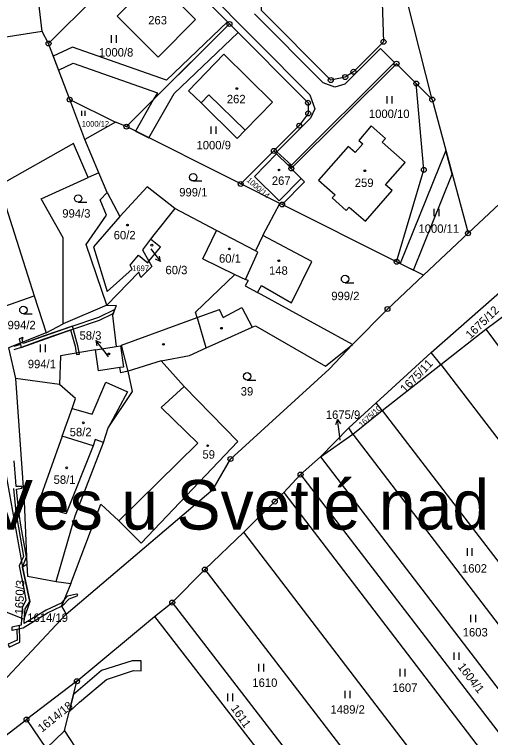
# Model space of a CAD drawing. Extents: x -680203 to -673936, y -1102717 to -1093650.
# Drawn here: x -676580.5 to -676484.3, y -1100983.9 to -1100837.8 of the extents above; entities that cross this region are included whole.
import ezdxf

# ---------------------------------------------------------------- set-up
doc = ezdxf.new("R2010")
doc.units = 0
for name, color, linetype in [('SOxx02xx_Koleje_param další_Popis10', 7, 'Continuous'), ('SOxx02xx_Staničení_Popis10', 7, 'Continuous'), ('SOxxxxxx_Koleje_hlavní_body_Popis10', 7, 'Continuous'), ('SOxxxxxx_Koleje_LN_parametry_Popis10', 7, 'Continuous'), ('SOxxxxxx_Koleje_param další_Popis10', 7, 'Continuous'), ('SOxxxxxx_Osa_bod_P', 7, 'Continuous'), ('SOxxxxxx_Staničení_Popis10', 7, 'Continuous'), ('x_prac', 7, 'Continuous')]:
    doc.layers.add(name, color=color, linetype=linetype)

msp = doc.modelspace()

# ---------------------------------------------------------------- linework, layer by layer
at = {"layer": 'SOxx02xx_Koleje_param další_Popis10'}
for centre, radius in [((-676537.07, -1100839.74), 0.5), ((-676537.07, -1100839.74), 0.0303), ((-676505.95, -1100843.34), 0.5), ((-676573.65, -1100843.69), 0.5), ((-676573.65, -1100843.69), 0.0303), ((-676505.95, -1100843.34), 0.0303), ((-676503.33, -1100847.76), 0.5), ((-676503.33, -1100847.76), 0.0303), ((-676513.7, -1100850.47), 0.5), ((-676512.04, -1100849.4), 0.5), ((-676512.04, -1100849.4), 0.0303), ((-676516.62, -1100851.07), 0.5), ((-676516.62, -1100851.07), 0.0303), ((-676513.7, -1100850.47), 0.0303), ((-676499.34, -1100851.78), 0.5), ((-676499.34, -1100851.78), 0.0303), ((-676569.37, -1100855.03), 0.5), ((-676496.12, -1100855.01), 0.5), ((-676569.37, -1100855.03), 0.0303), ((-676521.22, -1100855.66), 0.5), ((-676521.22, -1100855.66), 0.0303), ((-676496.12, -1100855.01), 0.0303), ((-676521.18, -1100857.82), 0.5), ((-676521.18, -1100857.82), 0.0303), ((-676557.91, -1100860.48), 0.5), ((-676522.98, -1100860.28), 0.5), ((-676522.98, -1100860.28), 0.0303), ((-676557.91, -1100860.48), 0.0303), ((-676528.12, -1100865.39), 0.5), ((-676528.12, -1100865.39), 0.0303), ((-676524.59, -1100868.94), 0.5), ((-676524.59, -1100868.94), 0.0303), ((-676497.82, -1100869.21), 0.5), ((-676497.82, -1100869.21), 0.0303), ((-676534.82, -1100872.06), 0.5), ((-676534.82, -1100872.06), 0.0303), ((-676526.44, -1100876.21), 0.5), ((-676526.44, -1100876.21), 0.0303), ((-676488.89, -1100882.02), 0.5), ((-676488.89, -1100882.02), 0.0303), ((-676503.31, -1100887.77), 0.5), ((-676503.31, -1100887.77), 0.0303), ((-676505.16, -1100897.32), 0.5), ((-676505.16, -1100897.32), 0.0303), ((-676536.89, -1100927.63), 0.5), ((-676536.89, -1100927.63), 0.0303), ((-676522.72, -1100930.77), 0.5), ((-676522.72, -1100930.77), 0.0303), ((-676527.93, -1100936.22), 0.5), ((-676527.93, -1100936.22), 0.0303), ((-676542.07, -1100949.94), 0.5), ((-676542.07, -1100949.94), 0.0303), ((-676548.66, -1100956.62), 0.5), ((-676548.66, -1100956.62), 0.0303), ((-676567.91, -1100972.52), 0.5), ((-676567.91, -1100972.52), 0.0303), ((-676578.1, -1100980.26), 0.5), ((-676578.1, -1100980.26), 0.0303)]:
    msp.add_circle(centre, radius, dxfattribs=at)
at = {"layer": 'SOxx02xx_Staničení_Popis10'}
for p, q in [((-676553.01, -1100885.15), (-676552.85, -1100885.36)), ((-676552.85, -1100885.36), (-676551, -1100887.73)), ((-676551, -1100887.73), (-676551.22, -1100886.63)), ((-676551, -1100887.73), (-676552.01, -1100887.24)), ((-676562.23, -1100906.06), (-676564.08, -1100903.7)), ((-676564.08, -1100903.7), (-676563.07, -1100904.18)), ((-676564.08, -1100903.7), (-676563.86, -1100904.79)), ((-676561.55, -1100906.96), (-676562.23, -1100906.06)), ((-676515.29, -1100919.63), (-676515.64, -1100920.69)), ((-676514.87, -1100922.6), (-676515.29, -1100919.63)), ((-676515.29, -1100919.63), (-676514.65, -1100920.55)), ((-676514.71, -1100923.8), (-676514.87, -1100922.6))]:
    msp.add_line(p, q, dxfattribs=at)
at = {"layer": 'SOxxxxxx_Koleje_hlavní_body_Popis10'}
for p, q in [((-676560.9, -1100843.53), (-676560.9, -1100842.03)), ((-676559.9, -1100843.53), (-676559.9, -1100842.03)), ((-676505.21, -1100855.8), (-676505.21, -1100854.3)), ((-676504.21, -1100855.8), (-676504.21, -1100854.3)), ((-676566.91, -1100858.32), (-676566.91, -1100857.31)), ((-676566.24, -1100858.32), (-676566.24, -1100857.31)), ((-676540.76, -1100861.95), (-676540.76, -1100860.45)), ((-676539.76, -1100861.95), (-676539.76, -1100860.45)), ((-676544.41, -1100871.46), (-676542.66, -1100871.46)), ((-676567.65, -1100875.74), (-676565.9, -1100875.74)), ((-676495.71, -1100878.6), (-676495.71, -1100877.1)), ((-676494.71, -1100878.6), (-676494.71, -1100877.1)), ((-676513.73, -1100892.01), (-676511.98, -1100892.01)), ((-676578.73, -1100898.28), (-676576.98, -1100898.28)), ((-676575.26, -1100906.01), (-676575.26, -1100904.51)), ((-676574.26, -1100906.01), (-676574.26, -1100904.51)), ((-676533.52, -1100911.68), (-676531.77, -1100911.68)), ((-676489.02, -1100947.15), (-676489.02, -1100945.65)), ((-676488.02, -1100947.15), (-676488.02, -1100945.65)), ((-676488.33, -1100960.59), (-676488.33, -1100959.09)), ((-676487.33, -1100960.59), (-676487.33, -1100959.09)), ((-676491.69, -1100968.19), (-676491.69, -1100966.69)), ((-676490.69, -1100968.19), (-676490.69, -1100966.69)), ((-676531.14, -1100970.52), (-676531.14, -1100969.02)), ((-676530.14, -1100970.52), (-676530.14, -1100969.02)), ((-676502.57, -1100971.54), (-676502.57, -1100970.04)), ((-676501.57, -1100971.54), (-676501.57, -1100970.04)), ((-676537.43, -1100976.51), (-676537.43, -1100975.01)), ((-676536.43, -1100976.51), (-676536.43, -1100975.01)), ((-676513.68, -1100975.95), (-676513.68, -1100974.45)), ((-676512.68, -1100975.95), (-676512.68, -1100974.45))]:
    msp.add_line(p, q, dxfattribs=at)
for centre in [(-676544.41, -1100870.71), (-676567.65, -1100874.99), (-676513.73, -1100891.26), (-676578.73, -1100897.53), (-676533.52, -1100910.93)]:
    msp.add_circle(centre, 0.75, dxfattribs=at)
at = {"layer": 'SOxxxxxx_Koleje_LN_parametry_Popis10'}
for points in [[(-676552.48, -1100855.08), (-676537.07, -1100839.74), (-676537.48, -1100839.33), (-676549.84, -1100851.11), (-676568.84, -1100844.43), (-676572.68, -1100846.26), (-676571.63, -1100849.06), (-676568.67, -1100847.67), (-676551.66, -1100853.64)], [(-676548.27, -1100853.76), (-676535.36, -1100841.46), (-676537.07, -1100839.74), (-676552.48, -1100855.08), (-676556.09, -1100861.4), (-676553.41, -1100862.74)], [(-676493.37, -1100865.28), (-676502.61, -1100888.12), (-676499.92, -1100889.46), (-676492.09, -1100870.08)], [(-676579.2, -1100905.11), (-676568.91, -1100901.46), (-676563.36, -1100899.57), (-676560.57, -1100898.24), (-676560.28, -1100897.44), (-676563.58, -1100899.01), (-676569.11, -1100900.9), (-676578.78, -1100904.31), (-676578.85, -1100904.01), (-676579.41, -1100904.23)], [(-676578.85, -1100904.01), (-676579.01, -1100903.36), (-676578.79, -1100903.28), (-676578.87, -1100903.07), (-676579.58, -1100903.34), (-676579.37, -1100904.22)], [(-676567.39, -1100906.42), (-676567.44, -1100906.13), (-676568.04, -1100906.23), (-676567.98, -1100906.53)], [(-676570.49, -1100956.08), (-676571.01, -1100957.33), (-676570.76, -1100957.23), (-676569.47, -1100955.87), (-676567.85, -1100955.26), (-676567.75, -1100954.97), (-676567.97, -1100954.9), (-676569.79, -1100955.35)], [(-676579.42, -1100964.61), (-676579.49, -1100961.26), (-676581.06, -1100961.59), (-676581.04, -1100962.18), (-676580.07, -1100962), (-676580.02, -1100964.23), (-676581.78, -1100965.05), (-676581.61, -1100965.64)], [(-676562.96, -1100970.38), (-676568.58, -1100975.17), (-676569.47, -1100978.73), (-676567.36, -1100976.76), (-676561.97, -1100972.16), (-676556.45, -1100970.38), (-676554.95, -1100970.42), (-676554.9, -1100968.42), (-676556.74, -1100968.38)]]:
    msp.add_lwpolyline(points, close=True, dxfattribs=at)
for points in [[(-676580.58, -1100905.53), (-676578.89, -1100904.99), (-676574.53, -1100903.37), (-676569.21, -1100901.56), (-676568.29, -1100904.86), (-676568.04, -1100906.23), (-676567.44, -1100906.13), (-676567.7, -1100904.75), (-676568.81, -1100900.8), (-676574.73, -1100902.81), (-676578.78, -1100904.31), (-676578.85, -1100904.01), (-676579.37, -1100904.22), (-676579.32, -1100904.5), (-676580.63, -1100904.92)], [(-676581.03, -1100962.22), (-676578.78, -1100961.7), (-676573.85, -1100958.7), (-676571.01, -1100957.33), (-676570.49, -1100956.08), (-676571.12, -1100956.73), (-676574.13, -1100958.18), (-676578.56, -1100960.87), (-676578.48, -1100959.46), (-676578.39, -1100957.86), (-676577.42, -1100956.4), (-676578.91, -1100949.49), (-676578.11, -1100947.4), (-676579.15, -1100941.37), (-676579.67, -1100938.29), (-676580.11, -1100933.74), (-676579.02, -1100933.5), (-676579.01, -1100933.17), (-676580.16, -1100933.18), (-676580.27, -1100932.15), (-676580.56, -1100928)], [(-676580.73, -1100933.56), (-676580.27, -1100938.37), (-676579.75, -1100941.47), (-676578.72, -1100947.32), (-676579.14, -1100948.19), (-676579.61, -1100949.18), (-676578.61, -1100953.83), (-676578.21, -1100956.14), (-676578.99, -1100957.7), (-676579.1, -1100959.82), (-676579.18, -1100961.18), (-676581.06, -1100961.61)]]:
    msp.add_lwpolyline(points, dxfattribs=at)
at = {"layer": 'SOxxxxxx_Koleje_param další_Popis10'}
for centre in [(-676535.58, -1100852.79), (-676527.08, -1100869.24), (-676509.72, -1100869.39), (-676557.71, -1100880.37), (-676552.77, -1100884.42), (-676537.12, -1100885.18), (-676527.11, -1100887.58), (-676538.72, -1100901.2), (-676550.44, -1100904.46), (-676561.48, -1100906.39), (-676566.62, -1100920.31), (-676541.5, -1100924.93), (-676569.98, -1100929.4)]:
    msp.add_circle(centre, 0.175, dxfattribs=at)
at = {"layer": 'SOxxxxxx_Staničení_Popis10'}
for p, q in [((-676542.84, -1100855.67), (-676541.23, -1100854.03)), ((-676541.23, -1100854.03), (-676533.95, -1100861.17)), ((-676525.19, -1100868.34), (-676524.83, -1100868.7)), ((-676583.69, -1100872.39), (-676576.54, -1100894.64)), ((-676542.46, -1100887.2), (-676539.7, -1100881.46)), ((-676542.46, -1100887.2), (-676536.01, -1100890.37)), ((-676533.33, -1100891.54), (-676533.95, -1100892.65)), ((-676533.33, -1100891.54), (-676533.85, -1100891.33)), ((-676533.95, -1100892.65), (-676531.41, -1100893.98)), ((-676543.61, -1100899.04), (-676539.11, -1100897.4)), ((-676538.38, -1100899.04), (-676539.11, -1100897.4)), ((-676538.38, -1100899.04), (-676534.62, -1100897.05)), ((-676534.62, -1100897.05), (-676532.51, -1100901.02)), ((-676558.93, -1100904.62), (-676543.61, -1100899.04)), ((-676557.56, -1100909.88), (-676558.93, -1100904.62)), ((-676564.86, -1100918.59), (-676562.1, -1100912.09)), ((-676562.1, -1100912.09), (-676557.72, -1100914.08)), ((-676557.72, -1100914.08), (-676561.58, -1100921.3)), ((-676546.25, -1100913), (-676550.91, -1100917.24)), ((-676550.91, -1100917.24), (-676543.47, -1100924.45)), ((-676568.89, -1100917.42), (-676564.86, -1100918.59)), ((-676570.87, -1100922.98), (-676575.9, -1100937.01)), ((-676543.47, -1100924.45), (-676559.47, -1100940.1)), ((-676564.6, -1100924.95), (-676570.07, -1100938.66)), ((-676575.9, -1100937.01), (-676570.07, -1100938.66))]:
    msp.add_line(p, q, dxfattribs=at)
at = {"layer": 'x_prac'}
for p, q in [((-676574.95, -1100841.25), (-676579.72, -1100801.4)), ((-676573.65, -1100843.69), (-676553.3, -1100823.44)), ((-676553.3, -1100823.44), (-676537.07, -1100839.74)), ((-676557.91, -1100860.48), (-676537.07, -1100839.74)), ((-676574.95, -1100841.25), (-676593.79, -1100844.19)), ((-676573.65, -1100843.69), (-676574.95, -1100841.25)), ((-676569.37, -1100855.03), (-676573.65, -1100843.69)), ((-676497.82, -1100869.21), (-676499.34, -1100851.78)), ((-676499.34, -1100851.78), (-676496.12, -1100855.01)), ((-676569.37, -1100855.03), (-676560.11, -1100859.6)), ((-676566.3, -1100863.11), (-676569.37, -1100855.03)), ((-676496.12, -1100855.01), (-676488.89, -1100882.02)), ((-676560.11, -1100859.6), (-676566.3, -1100863.11)), ((-676557.91, -1100860.48), (-676560.11, -1100859.6)), ((-676534.82, -1100872.06), (-676557.91, -1100860.48)), ((-676563.48, -1100869.8), (-676566.3, -1100863.11)), ((-676534.82, -1100872.06), (-676528.12, -1100865.39)), ((-676528.12, -1100865.39), (-676527.57, -1100865.95)), ((-676522.63, -1100870.94), (-676524.59, -1100868.94)), ((-676563.48, -1100869.8), (-676565.64, -1100870.73)), ((-676561.83, -1100873.76), (-676563.48, -1100869.8)), ((-676503.31, -1100887.77), (-676497.82, -1100869.21)), ((-676526.91, -1100875.99), (-676534.82, -1100872.06)), ((-676521.93, -1100871.65), (-676526.44, -1100876.21)), ((-676522.63, -1100870.94), (-676521.93, -1100871.65)), ((-676561.83, -1100873.76), (-676559.24, -1100878.61)), ((-676530.35, -1100882.47), (-676526.91, -1100875.99)), ((-676526.44, -1100876.21), (-676526.91, -1100875.99)), ((-676503.31, -1100887.77), (-676526.44, -1100876.21)), ((-676488.89, -1100882.02), (-676481.47, -1100875.04)), ((-676488.89, -1100882.02), (-676497.86, -1100890.48)), ((-676530.35, -1100882.47), (-676531.83, -1100885.6)), ((-676497.86, -1100890.48), (-676503.31, -1100887.77)), ((-676496.34, -1100906.08), (-676480.26, -1100891.99)), ((-676561.9, -1100896.53), (-676570.7, -1100900.34)), ((-676485.32, -1100901.42), (-676477.57, -1100895.67)), ((-676574.16, -1100902.14), (-676570.7, -1100900.34)), ((-676574.16, -1100902.14), (-676581.73, -1100905.16)), ((-676494.4, -1100908.54), (-676485.32, -1100901.42)), ((-676485.32, -1100901.42), (-676461.19, -1100934)), ((-676581.73, -1100905.16), (-676580.34, -1100911.36)), ((-676564.18, -1100905.58), (-676560, -1100904.88)), ((-676560, -1100904.88), (-676559.14, -1100904.74)), ((-676559.14, -1100904.74), (-676558.52, -1100909.06)), ((-676507.46, -1100916.27), (-676496.34, -1100906.08)), ((-676494.4, -1100908.54), (-676496.34, -1100906.08)), ((-676550.87, -1100907.8), (-676557.56, -1100909.88)), ((-676506.21, -1100917.85), (-676494.4, -1100908.54)), ((-676494.4, -1100908.54), (-676469.06, -1100941.58)), ((-676558.52, -1100909.06), (-676559.21, -1100909.16)), ((-676571.43, -1100912.59), (-676580.34, -1100911.36)), ((-676512.95, -1100921.3), (-676507.46, -1100916.27)), ((-676506.21, -1100917.85), (-676507.46, -1100916.27)), ((-676512.14, -1100922.61), (-676506.21, -1100917.85)), ((-676506.21, -1100917.85), (-676454.36, -1100985.53)), ((-676518.69, -1100927.16), (-676512.95, -1100921.3)), ((-676512.14, -1100922.61), (-676512.95, -1100921.3)), ((-676518.69, -1100927.16), (-676512.14, -1100922.61)), ((-676512.14, -1100922.61), (-676458.6, -1100992.67)), ((-676583.29, -1100924.99), (-676578.91, -1100949.49)), ((-676522.72, -1100930.77), (-676518.69, -1100927.16)), ((-676518.69, -1100927.16), (-676462.89, -1101000.14)), ((-676526.09, -1100934.37), (-676522.72, -1100930.77)), ((-676522.72, -1100930.77), (-676464.92, -1101006.1)), ((-676526.09, -1100934.37), (-676466.86, -1101011.76)), ((-676542.07, -1100949.94), (-676534.21, -1100942.4)), ((-676470.34, -1101025.78), (-676534.21, -1100942.4)), ((-676578.04, -1100948.93), (-676578.91, -1100949.49)), ((-676548.66, -1100956.62), (-676542.07, -1100949.94)), ((-676542.07, -1100949.94), (-676507.85, -1100994.4)), ((-676572.09, -1100952.4), (-676569.13, -1100952.77)), ((-676552.26, -1100959.44), (-676548.66, -1100956.62)), ((-676548.66, -1100956.62), (-676514.94, -1101000.3)), ((-676585.17, -1100975.07), (-676570.1, -1100958.94)), ((-676567.91, -1100972.52), (-676552.26, -1100959.44)), ((-676552.26, -1100959.44), (-676518.17, -1101003.34)), ((-676567.91, -1100972.52), (-676578.1, -1100980.26)), ((-676570.43, -1100982.53), (-676567.91, -1100972.52)), ((-676592.72, -1100991.36), (-676578.1, -1100980.26)), ((-676578.1, -1100980.26), (-676574.15, -1100986.08)), ((-676574.15, -1100986.08), (-676570.43, -1100982.53)), ((-676570.43, -1100982.53), (-676566.51, -1100988.48))]:
    msp.add_line(p, q, dxfattribs=at)
for points in [[(-676502.98, -1100809.33), (-676496.95, -1100812.05), (-676506.66, -1100823.48), (-676505.95, -1100843.34), (-676512.04, -1100849.4), (-676513.7, -1100850.47), (-676516.62, -1100851.07), (-676530.62, -1100837.01), (-676530.61, -1100833.47)], [(-676496.12, -1100855.01), (-676501.2, -1100835.05), (-676503.82, -1100826.27), (-676498.92, -1100820), (-676491.58, -1100824.01), (-676489.06, -1100817.06)], [(-676546.96, -1100830.61), (-676549.61, -1100828), (-676559.78, -1100838.17), (-676551.51, -1100846.45), (-676543.95, -1100838.86), (-676549.57, -1100833.24), (-676546.96, -1100830.61)], [(-676542.41, -1100832.29), (-676520.82, -1100854.03), (-676519.82, -1100856.89), (-676520.69, -1100858.76), (-676527.55, -1100865.59), (-676524.54, -1100868.25), (-676503.77, -1100847.53), (-676506.55, -1100844.71), (-676513.8, -1100851.93), (-676515.79, -1100852.52), (-676518.15, -1100851.65), (-676532.03, -1100837.67)], [(-676537.07, -1100839.74), (-676521.22, -1100855.66), (-676521.18, -1100857.82), (-676522.98, -1100860.28), (-676528.12, -1100865.39)], [(-676528.41, -1100855.55), (-676538.22, -1100845.81), (-676545.4, -1100853.25), (-676542.84, -1100855.67), (-676535.56, -1100862.86), (-676533.95, -1100861.17), (-676528.41, -1100855.55)], [(-676524.59, -1100868.94), (-676503.33, -1100847.76), (-676499.34, -1100851.78)], [(-676513.51, -1100877.42), (-676512.91, -1100876.73), (-676509.62, -1100879.59), (-676504.22, -1100873.39), (-676505.57, -1100872.23), (-676501.58, -1100867.74), (-676506.23, -1100863.62), (-676505.57, -1100862.88), (-676508.44, -1100860.32), (-676510.98, -1100863.25), (-676510.16, -1100863.94), (-676511.69, -1100865.7), (-676513.13, -1100864.48), (-676519.12, -1100871.27), (-676515.75, -1100874.29), (-676516.31, -1100874.88), (-676513.51, -1100877.42)], [(-676565.64, -1100870.73), (-676568.6, -1100863.91), (-676583.69, -1100872.39), (-676590.55, -1100874.87)], [(-676527.57, -1100865.95), (-676532.06, -1100870.56), (-676527.04, -1100875.46), (-676522.63, -1100870.94)], [(-676524.59, -1100868.94), (-676524.83, -1100868.7), (-676524.65, -1100868.51), (-676525, -1100868.16), (-676525.19, -1100868.34), (-676527.57, -1100865.95)], [(-676570.7, -1100900.34), (-676570.7, -1100882.96), (-676575.11, -1100875.06), (-676565.64, -1100870.73)], [(-676548.14, -1100877.03), (-676553.75, -1100872.65), (-676559.24, -1100878.61)], [(-676561.9, -1100896.53), (-676566.02, -1100884.31), (-676561.97, -1100878.38), (-676563.19, -1100875.27), (-676561.83, -1100873.76)], [(-676548.14, -1100877.03), (-676552.34, -1100882.35), (-676553.07, -1100883.22)], [(-676531.83, -1100885.6), (-676539.7, -1100881.46), (-676548.14, -1100877.03)], [(-676559.24, -1100878.61), (-676564.57, -1100884.78), (-676561.79, -1100893.78), (-676556.75, -1100889.28), (-676557.15, -1100888.48), (-676555.49, -1100886.45), (-676553.61, -1100887.98), (-676553.37, -1100887.68)], [(-676553.07, -1100883.22), (-676554.68, -1100885.37), (-676553.37, -1100887.68)], [(-676553.37, -1100887.68), (-676551.04, -1100884.82), (-676553.07, -1100883.22)], [(-676512.26, -1100904.49), (-676531.41, -1100893.98), (-676530.6, -1100892.57), (-676524.53, -1100896.08), (-676520.44, -1100887.74), (-676530.35, -1100882.47)], [(-676541.8, -1100905.18), (-676543.51, -1100899.37), (-676543.61, -1100899.04), (-676543.92, -1100897.96), (-676536.01, -1100890.37), (-676533.85, -1100891.33), (-676531.36, -1100885.84), (-676531.83, -1100885.6)], [(-676553.37, -1100887.68), (-676552.8, -1100888.71), (-676555.01, -1100890.94), (-676555.41, -1100889.89), (-676561.9, -1100896.53)], [(-676512.26, -1100904.49), (-676505.16, -1100897.32), (-676497.86, -1100890.48)], [(-676583.66, -1100897.16), (-676576.54, -1100894.64), (-676574.16, -1100902.14)], [(-676561.9, -1100896.53), (-676560, -1100896.64), (-676560.71, -1100898.64), (-676560, -1100904.88)], [(-676541.8, -1100905.18), (-676536.66, -1100902.87), (-676532.51, -1100901.02), (-676531.82, -1100900.71), (-676517.67, -1100908.86), (-676512.26, -1100904.49)], [(-676564.18, -1100905.58), (-676571.21, -1100906.77), (-676571.43, -1100912.59)], [(-676570.1, -1100958.94), (-676540.4, -1100933.7), (-676536.89, -1100927.63), (-676516.95, -1100909.45), (-676512.26, -1100904.49)], [(-676559.21, -1100909.16), (-676563.58, -1100909.78), (-676564.18, -1100905.58)], [(-676550.87, -1100907.8), (-676545.19, -1100906.69), (-676541.8, -1100905.18)], [(-676569.13, -1100952.77), (-676563.09, -1100936.75), (-676559.47, -1100940.1), (-676554.96, -1100944.6), (-676535.37, -1100924.12), (-676546.25, -1100913), (-676550.87, -1100907.8)], [(-676562.54, -1100924.27), (-676561.58, -1100921.3), (-676556.71, -1100913.98), (-676557.56, -1100909.88)], [(-676557.56, -1100909.88), (-676559.02, -1100910.21), (-676559.21, -1100909.16)], [(-676580.34, -1100911.36), (-676578.59, -1100936.24), (-676578.04, -1100948.93)], [(-676562.54, -1100924.27), (-676564.21, -1100923.69), (-676564.6, -1100924.95), (-676570.87, -1100922.98), (-676568.89, -1100917.42), (-676568.23, -1100915.39), (-676571.43, -1100912.59)], [(-676572.09, -1100952.4), (-676568.27, -1100939.1), (-676562.54, -1100924.27)], [(-676534.21, -1100942.4), (-676527.93, -1100936.22), (-676526.09, -1100934.37)], [(-676578.04, -1100948.93), (-676577.91, -1100951.26), (-676572.09, -1100952.4)], [(-676578.91, -1100949.49), (-676577.42, -1100956.4), (-676578.67, -1100960), (-676582.57, -1100958.42)], [(-676569.13, -1100952.77), (-676571.01, -1100957.33), (-676570.1, -1100958.94)]]:
    msp.add_lwpolyline(points, dxfattribs=at)

# ---------------------------------------------------------------- texts
at = {"layer": 'SOxx02xx_Staničení_Popis10'}
msp.add_text('Nová Ves u Svetlé nad Sázavou 705985', height=10, dxfattribs=at).set_placement((-676620.65, -1100941.87))
at = {"layer": 'SOxxxxxx_Osa_bod_P'}
for s, height, p in [('263', 1.7, (-676553.51, -1100839.83)), ('1000/8', 1.7, (-676563.47, -1100846.32)), ('262', 1.7, (-676537.62, -1100855.76)), ('1000/10', 1.7, (-676508.92, -1100858.74)), ('1000/12', 1.14, (-676566.93, -1100860.49)), ('1000/9', 1.7, (-676543.75, -1100865.07)), ('267', 1.7, (-676528.53, -1100872.24)), ('259', 1.7, (-676511.77, -1100872.67)), ('999/1', 1.7, (-676547.24, -1100874.58)), ('994/3', 1.7, (-676570.87, -1100878.86)), ('1000/11', 1.7, (-676498.9, -1100881.93)), ('60/2', 1.7, (-676560.48, -1100883.25)), ('60/1', 1.7, (-676539.2, -1100887.96)), ('1697', 1.14, (-676556.74, -1100889.67)), ('60/3', 1.7, (-676550.02, -1100890.3)), ('148', 1.7, (-676529.1, -1100890.4)), ('999/2', 1.7, (-676516.52, -1100895.53)), ('994/2', 1.7, (-676581.93, -1100901.41)), ('58/3', 1.7, (-676567.39, -1100903.52)), ('994/1', 1.7, (-676577.84, -1100909.28)), ('39', 1.7, (-676534.82, -1100914.8)), ('1675/9', 1.7, (-676517.62, -1100919.51)), ('58/2', 1.7, (-676569.37, -1100923.03)), ('59', 1.7, (-676542.55, -1100927.55)), ('58/1', 1.7, (-676572.62, -1100932.65)), ('1602', 1.7, (-676490.11, -1100950.57)), ('1614/19', 1.7, (-676577.95, -1100960.53)), ('1603', 1.7, (-676489.96, -1100963.47)), ('1610', 1.7, (-676532.47, -1100973.65)), ('1607', 1.7, (-676504.17, -1100974.67)), ('1489/2', 1.7, (-676516.69, -1100979.07))]:
    msp.add_text(s, height=height, dxfattribs=at).set_placement(p)
for s, height, rotation, p in [('1000/14', 1.14, 319, (-676533.72, -1100871.45)), ('1675/12', 1.7, 44, (-676488.39, -1100903.47)), ('1675/11', 1.7, 46, (-676501.55, -1100914.38)), ('1675/10', 1.14, 43, (-676510.33, -1100921.29)), ('1650/3', 1.7, 88, (-676578.76, -1100959.04)), ('1604/1', 1.7, 308, (-676491.08, -1100969.63)), ('1614/18', 1.7, 39, (-676574.97, -1100982.93)), ('1611', 1.7, 305, (-676536.91, -1100977.98))]:
    msp.add_text(s, height=height, rotation=rotation, dxfattribs=at).set_placement(p)

doc.saveas('drawing.dxf')
